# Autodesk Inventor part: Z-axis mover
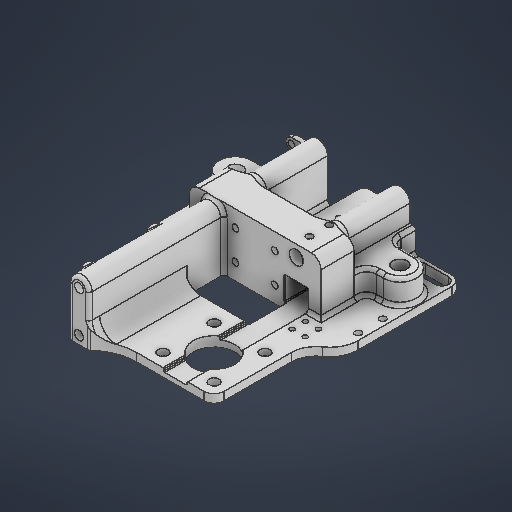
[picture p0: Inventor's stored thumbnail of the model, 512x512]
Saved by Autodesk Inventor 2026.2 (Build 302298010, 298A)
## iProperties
Created: 2026-04
Part Number: Z-axis mover
Material: 일반
Document SubType Name: Modeling
Designer: work
Density: 1 g/cm^3
Appearance: 기본값
Author: work
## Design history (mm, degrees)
sketch "스케치1"
  geometry: L1 (0, 0)-(8, 0); L2 (0, 0)-(0, 8); L3 (0, 0)-(-8, 0); L4 (0, 0)-(0, -8); L5 (0, 0)-(50, 0); L6 (0, 0)-(-50, 0); L7 (0, 0)-(0, 50); L8 (25, 0)-(25, -380); L9 (-25, 0)-(-25, -380); L10 (-25, 0)-(-25, 70); L11 (25, -380)-(-25, -380); L12 (25, 0)-(25, 0); L13 (25, 0)-(25, 120); L14 (-37.5, -395)-(37.5, -395); L15 (37.5, -395)-(37.5, -365); L16 (37.5, -365)-(-37.5, -365); L17 (-37.5, -365)-(-37.5, -395); L18 (-37.5, -395)-(37.5, -365); L19 (37.5, -395)-(-37.5, -365); L20 (-62.5, 38)-(62.5, 38); L21 (62.5, 38)-(62.5, -38); L22 (62.5, -38)-(-62.5, -38); L23 (-62.5, -38)-(-62.5, 38); L24 (-62.5, 38)-(62.5, -38); L25 (62.5, 38)-(-62.5, -38); L26 (62.5, -25)-(-62.5, -25); L27 (17, 38)-(-17, 38); L28 (-17, 38)-(-17, 61); L29 (-17, 61)-(17, 61); L30 (17, 61)-(17, 38); L31 (-22, 60.236)-(-22, 100); L32 (-22, 100)-(-28, 100); L33 (-28, 100)-(-28, -380); L34 (-28, -380)-(-22, -380); L35 (-22, -380)-(-22, 100); L36 (-40, 38)-(40, 38); L37 (40, 38)-(40, 18); L38 (40, 18)-(-40, 18); L39 (-40, 18)-(-40, 38); C1 r 5.25 at (0, 0); C2 r 11.3 at (0, 0); C3 r 2 at (8, 0); C4 r 2 at (0, 8); C5 r 2 at (-8, 0); C6 r 2 at (0, -8); C7 r 4.4 at (50, 0); C8 r 4.4 at (-50, 0); C9 r 4 at (0, 50); 7 further points
  constraints: 78 end point, 12 midpoint, 10 parallel, 9 centre point, 9 coincident, 8 horizontal, 6 perpendicular, 6 point on line, 5 vertical, 2 symmetric about line, 1 collinear, 22 other
  dimensions: "d0" = 10.5 diameter of C1; "d1" = 22.6 diameter of C2; "d2" = 8 distance of L1.start L1.end; "d3" = 4 diameter of C3; "d6" = 360 deg dimension on C1.centre L1.end (derived); "d8" = 50 distance of L4.start L5.end; "d9" = 8.8 diameter of C7; "d10" = 50 distance of L4.start L7.end; "d11" = 8 diameter of C9; "d12" = 12 distance of point (0, 38) L7.end; "d15" = 450 distance of L9.end L10.end; "d16" = 25 distance from line of point (0, 0) L8; "d17" = 25 distance from line of L10 C1.centre; "d19" = 500 distance of L8.end L13.end; "d20" = 120 vertical distance of point (0, 0) L13.end; "d21" = 75 distance between parallel lines of L17 L15; "d22" = 30 distance of L14.end L15.end; "d23" = 125 distance between parallel lines of L23 L21; "d24" = 25 distance from line of point (0, 0) L26; "d25" = 340 distance between parallel lines of L16 L26 (derived); "d26" = 34 distance of L28.end L29.end; "d27" = 23 distance of L27.end L28.end; "d30" = 6 distance between parallel lines of L33 L35; "d31" = 80 distance of L37.end L38.end; "d32" = 20 distance of L36.end L37.end; "d60" = 30 distance of L10.end point (-25, 100)
  node "스케치 - 원형 패턴1" dims "d6" = 360 deg (derived)
extrude "돌출1" new body sketch "스케치1" distance "d33" = 6; taper "d34" = 0 deg
extrude "돌출2" join sketch "스케치1" distance "d35" = 4; taper "d36" = 0 deg
extrude "돌출3" join sketch "스케치1" distance "d37" = 38; taper "d38" = 0 deg
sketch "스케치2"
  geometry: L1 (102.5, 6)-(22.5, 6) reference; L2 (87.5, 6)-(87.5, 31); L3 (93.5, 6)-(93.5, 31); L4 (81.5, 31)-(81.5, 6); L5 (0, 0)-(125, 0) reference; L6 (62.5, 6)-(37.5, 6); L7 (37.5, 6)-(37.5, 31); L8 (37.5, 31)-(62.5, 31); L9 (62.5, 31)-(62.5, 6); L10 (30.5, 4)-(44.5, 4); L11 (44.5, 4)-(44.5, 18); L12 (44.5, 18)-(30.5, 18); L13 (30.5, 18)-(30.5, 4); L14 (30.5, 4)-(44.5, 18); L15 (44.5, 4)-(30.5, 18); L16 (44.5, -10.5)-(86.5, -10.5); L17 (86.5, -10.5)-(86.5, 32.5); L18 (86.5, 32.5)-(44.5, 32.5); L19 (44.5, 32.5)-(44.5, -10.5); L20 (44.5, -10.5)-(86.5, 32.5); L21 (86.5, -10.5)-(44.5, 32.5); L22 (47.5, 32.5)-(47.5, -10.5); L23 (37.5, 6)-(37.5, 31); L24 (43.5, 6)-(43.5, 31); L25 (31.5, 31)-(31.5, 6); L26 (47, 1.5)-(28, 1.5); L27 (28, 1.5)-(28, 20.5); L28 (28, 20.5)-(47, 20.5); L29 (47, 20.5)-(47, 1.5); L30 (47, 1.5)-(28, 20.5); L31 (28, 1.5)-(47, 20.5); C1 r 2.75 at (87.5, 6); C2 r 2.75 at (87.5, 31); C3 r 4.25 at (37.5, 31); A1 r 6 centre (87.5, 6) between (81.5, 6) and (93.5, 6); A2 r 6 centre (87.5, 31) between (93.5, 31) and (81.5, 31); A3 r 6 centre (37.5, 6) between (31.5, 6) and (43.5, 6); A4 r 6 centre (37.5, 31) between (43.5, 31) and (31.5, 31); 16 further points
  constraints: 62 end point, 11 midpoint, 10 parallel, 10 tangent, 8 point on circle, 7 centre point, 7 perpendicular, 5 point on line, 4 horizontal, 2 coincident
  dimensions: "d39" = 5.5 diameter of C1; "d40" = 25 distance of L2.start L6.start; "d41" = 25 distance of L2.start L2.end; "d42" = 5.5 diameter of C2; "d43" = 25 distance of L7.end L8.end; "d44" = 25 distance of L6.end L7.end; "d45" = 8.5 diameter of C3; "d46" = 14 distance of L11.end L12.end; "d47" = 14 distance of L10.end L11.end; "d48" = 43 distance of L16.end L17.end; "d50" = 20 distance of L7.end point (37.5, 11); "d51" = 39 distance between parallel lines of L17 L22; "d52" = 3 distance between parallel lines of L22 L19; "d59" = 2.5 distance between parallel lines of L28 L12
extrude "돌출4" join sketch "스케치2" distance "d53" = 145; taper "d54" = 0 deg
extrude "돌출5" cut sketch "스케치2" extent not by distance; stored distance "d55" = 10; taper "d56" = 0 deg
sketch "스케치3"
  geometry: L1 (-31.5, 20.5)-(-31.5, 31) reference; L2 (-43.5, 31)-(-43.5, 20.5) reference; L3 (-30.5, 4)-(-44.5, 4) reference; L4 (-44.5, 18)-(-30.5, 18) reference; L5 (-28, 20.5)-(-31.5, 20.5) reference; L6 (-43.5, 20.5)-(-47, 20.5) reference; L7 (-47, 1.5)-(-41.469, 1.5) reference; L8 (-33.531, 1.5)-(-28, 1.5) reference; L9 (-28, 1.5)-(-28, 20.5) reference; L10 (-30.5, 18)-(-30.5, 4) reference; L11 (-44.5, 4)-(-44.5, 18) reference; L12 (-47, 20.5)-(-47, 1.5) reference; C1 r 6 at (-37.5, 31); A1 r 6 centre (-37.5, 6) between (-41.469, 1.5) and (-33.531, 1.5) reference; A2 r 6 centre (-37.5, 31) between (-31.5, 31) and (-43.5, 31) reference; 5 further points
  constraints: 1 centre point, 1 concentric
extrude "돌출6" cut sketch "스케치3" stored distance "d57" = 145; taper "d58" = 0 deg
sketch "스케치5"
  geometry: L1 (29.25, 38)-(20.75, 38) reference; L2 (18, 38)-(32, 38) reference; L3 (32, 38)-(18, 38) reference; L4 (-25, 38)-(62.5, 38) reference; L5 (40, 38)-(62.5, 38) reference; L6 (-40, 38)-(40, 38) reference; L7 (-62.5, 38)-(-40, 38) reference; L8 (-62.5, 38)-(-25, 38) reference; L9 (-25, 38)-(-31, 38) reference; L10 (-31, 38)-(-19, 38) reference; L11 (-19, 38)-(-25, 38) reference; L12 (25, 38)-(25, 88); L13 (9.5, 103.5)-(40.5, 103.5); L14 (40.5, 103.5)-(40.5, 72.5); L15 (40.5, 72.5)-(9.5, 72.5); L16 (9.5, 72.5)-(9.5, 103.5); L17 (9.5, 103.5)-(40.5, 72.5); L18 (40.5, 103.5)-(9.5, 72.5); L19 (1.5, 111.5)-(48.5, 111.5); L20 (48.5, 111.5)-(48.5, 64.5); L21 (48.5, 64.5)-(1.5, 64.5); L22 (1.5, 64.5)-(1.5, 111.5); L23 (1.5, 111.5)-(48.5, 64.5); L24 (48.5, 111.5)-(1.5, 64.5); L25 (-22.25, 120)-(-22.25, -25) reference; L26 (-31, 38)-(-19, 38) reference; L27 (-31, 38)-(-31, 120) reference; L28 (-19, 120)-(-31, 120) reference; L29 (-19, 38)-(-19, 120) reference; L30 (62.5, 38)-(62.5, -25) reference; L31 (40, 18)-(40, 38) reference; L32 (-62.5, 38)-(-25, 38) reference; L33 (-62.5, -25)-(-62.5, 38) reference; L34 (62.5, -25)-(-62.5, -25) reference; L35 (62.5, 38)-(62.5, -25) reference; L36 (-25, 38)-(62.5, 38) reference; L37 (-19, 38)-(19, 38); L38 (19, 38)-(19, 62); L39 (19, 62)-(-19, 62); L40 (-19, 62)-(-19, 38); L41 (-19, 38)-(-19, 120) reference; C1 r 12.5 at (25, 88); C2 r 2 at (9.5, 72.5); C3 r 2 at (40.5, 103.5); C4 r 2 at (9.5, 103.5); C5 r 2 at (40.5, 72.5); C6 r 2 at (0, -8) reference; C7 r 2 at (8, 0) reference; C8 r 2 at (0, 8) reference; C9 r 2 at (-8, 0) reference; C10 r 5.25 at (0, 0) reference; C11 r 4.4 at (50, 0) reference; C12 r 4.4 at (-50, 0) reference; A1 r 28.971 centre (1.5, 140.471) between (-19, 120) and (1.5, 111.5); A2 r 15 centre (63.5, 64.5) between (48.5, 64.5) and (55.046, 52.109); A3 r 17.08 centre (45.42, 38) between (62.5, 38) and (55.046, 52.109); 15 further points
  constraints: 34 end point, 8 centre point, 6 parallel, 6 point on circle, 5 coincident, 5 midpoint, 4 perpendicular, 4 tangent, 3 horizontal, 2 point on line, 5 other
  dimensions: "d61" = 25 distance from line of point (0, 38) L12; "d62" = 25 diameter of C1; "d63" = 31 distance of L14.end L15.end; "d64" = 31 distance of L13.end L14.end; "d65" = 4 diameter of C2; "d66" = 4 diameter of C3; "d67" = 4 diameter of C4; "d68" = 4 diameter of C5; "d69" = 50 distance of L12.start L12.end; "d70" = 8 distance between parallel lines of L14 L20; "d71" = 15 radius of A2; "d73" = 24 distance of L39.end L37.start
extrude "돌출7" join sketch "스케치5" distance "d74" = 6; taper "d75" = 0 deg
sketch "스케치6"
  geometry: L1 (-81.5, 31)-(-81.5, 0) reference; L2 (-81.5, 0)-(-43.5, 0) reference; L3 (-43.5, 0)-(-43.5, 4) reference; L4 (-30.5, 6)-(-22.5, 6) reference; L5 (-44.5, 18)-(-44.5, 4) reference; L6 (-30.5, 18)-(-44.5, 18) reference; L7 (-30.5, 6)-(-30.5, 18) reference; L8 (-22.5, 6)-(-22.5, 38) reference; L9 (-102.5, 38)-(-22.5, 38) reference; L10 (-102.5, 6)-(-102.5, 38) reference; L11 (-125, 6)-(-102.5, 6) reference; L12 (-125, 0)-(-125, 6) reference; L13 (-125, 0)-(-93.5, 0) reference; L14 (-93.5, 0)-(-93.5, 31) reference; L15 (-81.5, 6)-(-81.5, 31) reference; L16 (-93.5, 31)-(-93.5, 0) reference; L17 (0, 0)-(-125, 0) reference; L18 (-93.5, 6)-(-81.5, 6); L19 (-81.5, 6)-(-81.5, 0); L20 (-81.5, 0)-(-93.5, 0); L21 (-93.5, 0)-(-93.5, 6); L22 (-81.5, 0)-(-93.5, 0) reference; L23 (-81.5, 0)-(-81.5, 6) reference; L24 (-90.25, 6)-(-84.75, 6) reference; L25 (-44.5, 4)-(-43.5, 4) reference; C1 r 4.25 at (-37.5, 31) reference; C2 r 2.75 at (-87.5, 31) reference; A1 r 6 centre (-87.5, 31) between (-81.5, 31) and (-93.5, 31) reference; A2 r 6 centre (-87.5, 31) between (-81.5, 31) and (-93.5, 31) reference; A3 r 2.75 centre (-87.5, 6) between (-84.75, 6) and (-90.25, 6) reference; 10 further points
  constraints: 8 end point, 2 parallel, 2 point on line, 1 horizontal, 1 perpendicular
extrude "돌출8" join sketch "스케치6" stored distance "d76" = 6; taper "d77" = 0 deg
sketch "스케치7"
  geometry: L1 (47, 6)-(81.5, 6) reference; L2 (47, 20.5)-(43.5, 20.5) reference; L3 (43.5, 20.5)-(43.5, 31) reference; L4 (31.5, 31)-(31.5, 20.5) reference; L5 (31.5, 20.5)-(28, 20.5) reference; L6 (28, 20.5)-(28, 6) reference; L7 (0, 6)-(28, 6) reference; L8 (0, 0)-(0, 6) reference; L9 (0, 0)-(125, 0) reference; L10 (125, 0)-(125, 6) reference; L11 (93.5, 6)-(125, 6) reference; L12 (93.5, 6)-(93.5, 31) reference; L13 (81.5, 31)-(81.5, 6) reference; L14 (44.5, 18)-(44.5, 4) reference; L15 (44.5, 4)-(30.5, 4) reference; L16 (30.5, 4)-(30.5, 18) reference; L17 (30.5, 18)-(44.5, 18) reference; L18 (43.5, 4)-(30.5, 4) reference; L19 (43.5, 4)-(43.5, 6) reference; L20 (30.5, 6)-(43.5, 6) reference; L21 (30.5, 4)-(30.5, 6) reference; L22 (81.5, 0)-(43.5, 0) reference; L23 (81.5, 0)-(81.5, 6) reference; L24 (43.5, 6)-(81.5, 6) reference; L25 (43.5, 0)-(43.5, 6) reference; L26 (47, 6)-(47, 20.5) reference; C1 r 2.75 at (87.5, 31) reference; C2 r 2.75 at (87.5, 6) reference; C3 r 2.75 at (87.5, 31) reference; A1 r 6 centre (37.5, 31) between (43.5, 31) and (31.5, 31) reference; A2 r 6 centre (87.5, 31) between (93.5, 31) and (81.5, 31) reference; 4 further points
extrude "돌출9" cut sketch "스케치7" extent not by distance; stored distance "d78" = 0; taper "d79" = 0 deg
sketch "스케치8"
  geometry: L1 (50.5, 10)-(74.5, 10); L2 (74.5, 10)-(74.5, 28); L3 (74.5, 28)-(50.5, 28); L4 (50.5, 28)-(50.5, 10); L5 (50.5, 10)-(74.5, 28); L6 (74.5, 10)-(50.5, 28); L7 (102.5, 38)-(22.5, 38) reference; L8 (62.5, 38)-(62.5, 0); C1 r 2 at (50.5, 28); C2 r 2 at (50.5, 10); C3 r 2 at (74.5, 10); C4 r 2 at (74.5, 28); 1 further point
  constraints: 14 end point, 4 centre point, 4 coincident, 4 midpoint, 2 parallel, 1 horizontal, 1 perpendicular, 1 vertical
  dimensions: "d80" = 24 distance of L3.end L2.end; "d81" = 18 distance of L2.end L1.end; "d82" = 4 diameter of C1; "d83" = 4 diameter of C2; "d84" = 4 diameter of C3; "d85" = 4 diameter of C4
extrude "돌출10" cut sketch "스케치8" extent not by distance; stored distance "d86" = 18 (derived); taper "d87" = 0 deg
sketch "스케치9"
  geometry: L1 (59, -32)-(59, -7) reference; L2 (71, -7)-(71, -32) reference; L3 (80, -32)-(71, -32) reference; L4 (80, -32)-(80, 0) reference; L5 (0, 0)-(80, 0) reference; L6 (0, -32)-(0, 0) reference; L7 (5.5, -32)-(0, -32) reference; L8 (5.5, -32)-(5.5, -17.5) reference; L9 (5.5, -17.5)-(9, -17.5) reference; L10 (9, -17.5)-(9, -7) reference; L11 (21, -7)-(21, -17.5) reference; L12 (21, -17.5)-(24.5, -17.5) reference; L13 (59, -32)-(24.5, -32) reference; L14 (24.5, -17.5)-(24.5, -32) reference; C1 r 2 at (28, -28) reference; C2 r 2 at (52, -28) reference; C3 r 2 at (28, -10) reference; C4 r 2 at (52, -10) reference; C5 r 2 at (52, -28) reference; A1 r 6 centre (65, -7) between (71, -7) and (59, -7) reference; A2 r 6 centre (15, -7) between (21, -7) and (9, -7) reference; 5 further points
  constraints: 4 coincident
hole "구멍1" sketch "스케치9" at (52, -10), (28, -10), (28, -28), (52, -28) diameter "d88" = 4; stored, may be unused: countersink angle "d92" = 90 deg, drill point angle "d94" = 0 deg; dims "d89" = 6, "d90" = 6.2, "d91" = 4, "d93" = 8
sketch "스케치10"
  geometry: L1 (32, -98.356)-(32, -111.5) reference; L2 (32, -111.5)-(48.5, -111.5) reference; L3 (48.5, -111.5)-(48.5, -64.5) reference; L4 (62.5, -38)-(62.5, 25) reference; L5 (62.5, 25)-(34.5, 25) reference; L6 (34.5, 25)-(34.5, -18) reference; L7 (34.5, -18)-(40, -18) reference; L8 (40, -18)-(40, -38) reference; L9 (32, -38)-(40, -38) reference; L10 (32, -38)-(32, -77.644) reference; L11 (-31, -18)-(-31, 25) reference; L12 (-31, 25)-(-62.5, 25) reference; L13 (-62.5, 25)-(-62.5, -38) reference; L14 (-62.5, -38)-(-40, -38) reference; L15 (-40, -38)-(-40, -18) reference; L16 (-40, -18)-(-31, -18) reference; L17 (-50, -10)-(-31, -10); L18 (-50, 10)-(-31, 10); L19 (50, 10)-(34.5, 10); L20 (50, -10)-(34.5, -10); C1 r 4.4 at (50, 0) reference; C2 r 2 at (40.5, -72.5) reference; C3 r 2 at (40.5, -103.5) reference; C4 r 4.4 at (-50, 0) reference; A1 r 15 centre (63.5, -64.5) between (55.046, -52.109) and (48.5, -64.5) reference; A2 r 17.08 centre (45.42, -38) between (55.046, -52.109) and (62.5, -38) reference; A3 r 12.5 centre (25, -88) between (32, -98.356) and (32, -77.644) reference; A4 r 10 centre (-50, 0) between (-50, -10) and (-50, 10); A5 r 10 centre (50, 0) between (50, 10) and (50, -10); 1 further point
  constraints: 8 end point, 4 perpendicular, 4 point on circle, 4 point on line, 4 tangent, 2 centre point, 2 coincident
  dimensions: "d95" = 20 diameter of A4; "d96" = 20 diameter of A5
extrude "돌출11" join sketch "스케치10" stored distance "d97" = 10; taper "d98" = 0 deg
fillet "모깎기1" dims "d99" = 6
sketch "스케치11"
  geometry: C1 r 4.25 at (0, 0) reference; 1 further point
extrude "돌출12" cut sketch "스케치11" extent not by distance; stored distance "d100" = 0; taper "d101" = 0 deg
fillet "모깎기2" dims "d102" = 2
fillet "모깎기3" dims "d103" = 0.5
chamfer "모따기1" distance "d104" = 1; stored, may be unused: second distance "d105" = 2, angle "d106" = 45 deg
sketch "스케치12"
  geometry: L1 (17.5, -61.936)-(17.5, -78) reference; L2 (17, -62)-(-17, -62) reference; L3 (-19, -60)-(-19, -118) reference; L4 (-21, -120)-(-19.813, -120) reference; L5 (1.5, -111.5)-(17.5, -111.5) reference; L6 (17.5, -98)-(17.5, -111.5) reference; L7 (42, -40)-(42, -17.621) reference; L8 (32.5, -78)-(32.5, -40) reference; L9 (32.5, -111.5)-(32.5, -98) reference; L10 (32.5, -111.5)-(42.5, -111.5) reference; L11 (48.5, -105.5)-(48.5, -64.5) reference; L12 (62.5, -38)-(62.5, 19) reference; L13 (56.5, 25)-(36.5, 25) reference; L14 (36.5, 16)-(36.5, 25) reference; L15 (50, 12)-(40.5, 12) reference; L16 (45.657, -12)-(50, -12) reference; L17 (42, -40)-(42, -17.621) reference; L18 (32.5, -40)-(42, -40) reference; C1 r 2 at (9.5, -72.5) reference; C2 r 2 at (9.5, -103.5) reference; C3 r 2 at (40.5, -103.5) reference; C4 r 2 at (40.5, -72.5) reference; C5 r 2 at (40.5, -103.5) reference; A1 r 2 centre (17, -60) between (17, -62) and (17.5, -61.936) reference; A2 r 2 centre (-17, -60) between (-19, -60) and (-17, -62) reference; A3 r 2 centre (-21, -118) between (-21, -120) and (-19, -118) reference; A4 r 2 centre (-19.813, -118) between (-19.813, -120) and (-18.437, -119.451) reference; A5 r 28.971 centre (1.5, -140.471) between (1.5, -111.5) and (-18.437, -119.451) reference; A6 r 12.5 centre (25, -88) between (17.5, -78) and (17.5, -98) reference; A7 r 12.5 centre (25, -88) between (32.5, -98) and (32.5, -78) reference; A8 r 6 centre (42.5, -105.5) between (42.5, -111.5) and (48.5, -105.5) reference; A9 r 15 centre (63.5, -64.5) between (55.046, -52.109) and (48.5, -64.5) reference; A10 r 17.08 centre (45.42, -38) between (55.046, -52.109) and (62.5, -38) reference; A11 r 6 centre (56.5, 19) between (62.5, 19) and (56.5, 25) reference; A12 r 4 centre (40.5, 16) between (36.5, 16) and (40.5, 12) reference; A13 r 12 centre (50, 0) between (50, -12) and (50, 12) reference; A14 r 4 centre (45.657, -16) between (45.657, -12) and (42, -17.621) reference; 5 further points
  constraints: 4 coincident
hole "구멍2" sketch "스케치12" at (9.5, -103.5), (40.5, -103.5), (40.5, -72.5), (9.5, -72.5) diameter "d107" = 4; stored, may be unused: countersink angle "d111" = 90 deg, drill point angle "d113" = 0 deg; dims "d108" = 6, "d109" = 6.2, "d110" = 4, "d112" = 8
fillet "모깎기4" dims "d114" = 10
sketch "스케치13"
  geometry: L1 (78, -30)-(0, -30) reference; L2 (78, 0)-(78, -30) reference; L3 (0, 0)-(78, 0) reference; L4 (0, -30)-(0, 0) reference; L5 (68, 0)-(28, 0); L6 (28, 0)-(28, -25); L7 (28, -25)-(68, -25); L8 (68, -25)-(68, 0); C1 r 4 at (28, 0); C2 r 4 at (28, -25); C3 r 4 at (68, -25); C4 r 4 at (68, 0); 1 further point
  constraints: 8 end point, 4 centre point, 2 parallel, 1 coincident, 1 horizontal, 1 perpendicular, 1 point on line
  dimensions: "d115" = 40 distance of L7.end L6.end; "d116" = 25 distance of L6.end L5.end; "d117" = 10 distance between parallel lines of L2 L8; "d118" = 8 diameter of C1; "d119" = 8 diameter of C2; "d120" = 8 diameter of C3; "d121" = 8 diameter of C4
  node "투영된 루프17"
extrude "돌출13" join sketch "스케치13" stored distance "d122" = 8 (derived); taper "d123" = 0 deg
extrude "돌출14" join sketch "스케치13" distance "d124" = 1.5; taper "d125" = 0 deg
sketch "스케치14"
  geometry: L1 (4, 0)-(36, 0) reference; L2 (-28, 0)-(-4, 0) reference; L3 (-28, -30)-(-28, 0) reference; L4 (50, -30)-(-28, -30) reference; L5 (50, 0)-(50, -30) reference; L6 (44, 0)-(50, 0) reference; C1 r 4 at (40, -25) reference; C2 r 4 at (0, -25) reference; C3 r 2 at (0, 0); C4 r 2 at (0, -25); C5 r 2 at (40, -25); C6 r 2 at (40, 0); A1 r 4 centre (40, 0) between (36, 0) and (44, 0) reference; A2 r 4 centre (0, 0) between (-4, 0) and (4, 0) reference; 1 further point
  constraints: 4 centre point, 4 coincident
  dimensions: "d126" = 4 diameter of C3; "d127" = 4 diameter of C4; "d128" = 4 diameter of C5; "d129" = 4 diameter of C6
  node "투영된 루프18"
extrude "돌출15" cut sketch "스케치14" stored distance "d130" = 1.5; taper "d131" = 0 deg
extrude "돌출16" cut sketch "스케치14" stored distance "d132" = 10; taper "d133" = 0 deg
fillet "모깎기5" dims "d134" = 2
sketch "스케치15"
  geometry: L1 (-21.127, -38)-(34, -38) reference; L2 (25, -38)-(25, -18); C1 r 2 at (25, -18); C2 r 2 at (25, -30); 1 further point
  constraints: 2 centre point, 2 end point, 2 point on line, 1 coincident, 1 vertical
  dimensions: "d135" = 20 distance of L2.start L2.end; "d136" = 25 distance from line of L2 point (0, 0); "d137" = 4 diameter of C1; "d138" = 4 diameter of C2; "d139" = 12 distance of L2.end C2.centre
extrude "돌출17" cut sketch "스케치15" stored distance "d140" = 10; taper "d141" = 0 deg
sketch "스케치16" dims "d145" = 7
  geometry: L1 (13, -21.5)-(13, -1.9); L2 (8, -25)-(31.5, -25) reference; L3 (6, -23)-(6, 0) reference; L4 (13, -5.4)-(6, -5.4); L5 (13, 1.6)-(5.783, 1.6); L6 (13, -18)-(6, -18); L7 (-42.5, -26.5)-(-42.5, -13.5) reference; L8 (-56.5, -27.5)-(-43.5, -27.5) reference; L9 (-57.5, -13.5)-(-57.5, -26.5) reference; L10 (-43.5, -12.5)-(-56.5, -12.5) reference; L11 (31.5, -30)-(-81.5, -30) reference; L12 (31.5, -25)-(31.5, -30) reference; L13 (8, -25)-(31.5, -25) reference; L14 (6, -23)-(6, 0) reference; L15 (-6, 0)-(-6, -23) reference; L16 (-38.5, -25)-(-8, -25) reference; L17 (-40.5, -23)-(-40.5, -12.5) reference; L18 (-42.5, -10.5)-(-44, -10.5) reference; L19 (-44, -10.5)-(-44, 0) reference; L20 (-56, 0)-(-56, -10.5) reference; L21 (-56, -10.5)-(-57.5, -10.5) reference; L22 (-59.5, -12.5)-(-59.5, -23) reference; L23 (-81.5, -25)-(-61.5, -25) reference; L24 (-81.5, -30)-(-81.5, -25) reference; C1 r 2 at (13, -21.5); C2 r 2 at (13, -1.9); C3 r 4.25 at (-50, 0) reference; C4 r 2.75 at (0, 0) reference; C5 r 2.75 at (0, -25) reference; A1 r 3.5 centre (13, -1.9) between (13, -5.4) and (13, 1.6); A2 r 6 centre (0, 0) between (6, 0) and (-6, 0) reference; A3 r 1 centre (-43.5, -13.5) between (-42.5, -13.5) and (-43.5, -12.5) reference; A4 r 1 centre (-43.5, -26.5) between (-43.5, -27.5) and (-42.5, -26.5) reference; A5 r 1 centre (-56.5, -26.5) between (-57.5, -26.5) and (-56.5, -27.5) reference; A6 r 1 centre (-56.5, -13.5) between (-56.5, -12.5) and (-57.5, -13.5) reference; A7 r 2 centre (8, -23) between (6, -23) and (8, -25) reference; A8 r 6 centre (0, 0) between (6, 0) and (-6, 0) reference; A9 r 2 centre (-8, -23) between (-8, -25) and (-6, -23) reference; A10 r 2 centre (-38.5, -23) between (-40.5, -23) and (-38.5, -25) reference; A11 r 2 centre (-42.5, -12.5) between (-40.5, -12.5) and (-42.5, -10.5) reference; A12 r 6 centre (-50, 0) between (-44, 0) and (-56, 0) reference; A13 r 2 centre (-57.5, -12.5) between (-57.5, -10.5) and (-59.5, -12.5) reference; A14 r 2 centre (-61.5, -23) between (-61.5, -25) and (-59.5, -23) reference; 5 further points
  constraints: 8 end point, 4 point on line, 3 centre point, 3 coincident, 3 perpendicular, 3 point on circle, 2 horizontal, 1 tangent, 1 vertical, 3 other
  dimensions: "d142" = 4 diameter of C1; "d143" = 4 diameter of C2; "d144" = 7 diameter of A1; "d146" = 19.6 distance of L1.start L1.end; "d147" = 7 distance from line of L3 L1.start
extrude "돌출18" join sketch "스케치16" distance "d148" = 3; taper "d149" = 0 deg
fillet "모깎기6" dims "d150" = 1
sketch "스케치17"
  geometry: L1 (0, 0)-(0, 25); L2 (13.5, 25)-(-17, 25) reference; L3 (7.5, 21)-(-7.5, 21); L4 (58.5, -34)-(58.5, -19); L5 (62.5, -38)-(62.5, 19) reference; C1 r 2 at (-7.5, 21); C2 r 2 at (7.5, 21); C3 r 2 at (58.5, -34); C4 r 2 at (58.5, -19); 1 further point
  constraints: 6 end point, 4 centre point, 4 coincident, 2 point on line, 2 vertical, 1 horizontal, 1 midpoint
  dimensions: "d151" = 15 distance of L3.start L3.end; "d152" = 4 diameter of C1; "d153" = 4 diameter of C2; "d154" = 4 distance between parallel lines of L2 L3; "d155" = 15 distance of L4.start L4.end; "d156" = 4 diameter of C3; "d157" = 4 diameter of C4; "d158" = 4 distance between parallel lines of L5 L4; "d159" = 4 horizontal distance of L5.start L4.start
extrude "돌출19" cut sketch "스케치17" extent not by distance; stored distance "d160" = 0; taper "d161" = 0 deg
sketch "스케치18"
  geometry: L1 (-42, -17.621)-(-42, -38) reference; L2 (-50, -12)-(-45.657, -12) reference; C1 r 16 at (-60, -30); 1 further point
  constraints: 1 centre point
  dimensions: "d162" = 32 diameter of C1; "d163" = 2 distance edge to line of C1 L1; "d164" = 2 distance edge to line of C1 L2
extrude "돌출20" cut sketch "스케치18" distance "d165" = 2; taper "d166" = 0 deg
sketch "스케치19"
  geometry: L1 (56.5, 19)-(42.5, 19); L2 (56.5, 23)-(42.5, 23); L3 (42.5, 15)-(56.5, 15); L4 (36.5, 16)-(36.5, 25) reference; L5 (-56.5, 19)-(-48, 19); L6 (-56.5, 15)-(-48, 15); L7 (-48, 23)-(-56.5, 23); L8 (-46.144, -38)-(-42, -38) reference; L9 (-42, -17.621)-(-42, -38) reference; L10 (-50, -12)-(-45.657, -12) reference; L11 (-37, 12)-(-50, 12) reference; L12 (-33, 21)-(-33, 16) reference; L13 (-41.742, 21)-(-33, 21) reference; L14 (-41.742, 25)-(-56.5, 25) reference; L15 (-62.5, 19)-(-62.5, -14.197) reference; L16 (36.5, -52)-(44.5, -52); L17 (44.5, -52)-(44.5, -44); L18 (44.5, -44)-(36.5, -44); L19 (36.5, -44)-(36.5, -52); L20 (32.5, -40)-(42, -40) reference; L21 (32.5, -78)-(32.5, -40) reference; L22 (13.5, 25)-(13.5, -16.011) reference; L23 (13.5, 25)-(-17, 25) reference; L24 (-17, -12)-(-17, 25) reference; L25 (9.631, -16)-(-9.631, -16) reference; L26 (32.5, -78)-(32.5, -40) reference; L27 (32.5, -111.5)-(32.5, -98) reference; L28 (32.5, -111.5)-(42.5, -111.5) reference; L29 (48.5, -105.5)-(48.5, -64.5) reference; L30 (62.5, -38)-(62.5, 19) reference; L31 (56.5, 25)-(36.5, 25) reference; L32 (36.5, 16)-(36.5, 25) reference; L33 (50, 12)-(40.5, 12) reference; L34 (45.657, -12)-(50, -12) reference; L35 (42, -40)-(42, -17.621) reference; L36 (32.5, -40)-(42, -40) reference; L37 (-41.742, 25)-(-41.742, 21) reference; C1 r 1.5 at (36.5, -52); C2 r 1.5 at (36.5, -44); C3 r 1.5 at (44.5, -44); C4 r 1.5 at (44.5, -52); A1 r 4 centre (56.5, 19) between (56.5, 15) and (56.5, 23); A2 r 4 centre (42.5, 19) between (42.5, 23) and (42.5, 15); A3 r 6 centre (56.5, 19) between (62.5, 19) and (56.5, 25) reference; A4 r 4 centre (-56.5, 19) between (-56.5, 23) and (-56.5, 15); A5 r 4 centre (-48, 19) between (-48, 15) and (-48, 23); A6 r 6 centre (-56.5, 19) between (-56.5, 25) and (-62.5, 19) reference; A7 r 16 centre (-60, -30) between (-46.144, -38) and (-62.5, -14.197) reference; A8 r 4 centre (-45.657, -16) between (-42, -17.621) and (-45.657, -12) reference; A9 r 12 centre (-50, 0) between (-50, 12) and (-50, -12) reference; A10 r 4 centre (-37, 16) between (-37, 12) and (-33, 16) reference; A11 r 6 centre (-56.5, 19) between (-56.5, 25) and (-62.5, 19) reference; A12 r 4 centre (-13, -12) between (-17, -12) and (-13.912, -15.895) reference; A13 r 12.5 centre (25, -88) between (32.5, -98) and (32.5, -78) reference; A14 r 6 centre (42.5, -105.5) between (42.5, -111.5) and (48.5, -105.5) reference; A15 r 15 centre (63.5, -64.5) between (55.046, -52.109) and (48.5, -64.5) reference; A16 r 17.08 centre (45.42, -38) between (55.046, -52.109) and (62.5, -38) reference; A17 r 6 centre (56.5, 19) between (62.5, 19) and (56.5, 25) reference; A18 r 4 centre (40.5, 16) between (36.5, 16) and (40.5, 12) reference; A19 r 12 centre (50, 0) between (50, -12) and (50, 12) reference; A20 r 4 centre (45.657, -16) between (45.657, -12) and (42, -17.621) reference; 8 further points
  constraints: 24 end point, 10 point on circle, 8 centre point, 8 tangent, 4 coincident, 4 parallel, 3 horizontal, 3 midpoint, 2 concentric, 1 perpendicular, 4 other
  dimensions: "d167" = 8 diameter of A2; "d168" = 2 distance from line of point (38.5, 19) L4; "d169" = 8 diameter of A5; "d171" = 3 diameter of C1; "d172" = 3 diameter of C2; "d173" = 3 diameter of C3; "d174" = 3 diameter of C4; "d175" = 8 distance of L16.end L17.end; "d176" = 8 distance of L17.end L18.end; "d177" = 4 distance between parallel lines of L20 L18; "d178" = 4 distance from line of L21 point (36.5, -48)
extrude "돌출21" cut sketch "스케치19" extent not by distance; stored distance "d179" = 0; taper "d180" = 0 deg
sketch "스케치20"
  geometry: L1 (13.5, 25)-(-17, 25) reference; L2 (-17, 25)-(13.5, 25); L3 (13.5, 25)-(13.5, 45); L4 (13.5, 45)-(-17, 45); L5 (-17, 45)-(-17, 25); L6 (13.5, 25)-(13.5, -16.011) reference; L7 (-17, 25)-(13.5, 25); L8 (13.5, 25)-(13.5, 23.5); L9 (13.5, 23.5)-(-17, 23.5); L10 (-17, 23.5)-(-17, 25); 1 further point
  constraints: 16 end point, 4 parallel, 2 horizontal, 2 perpendicular, 2 point on line
  dimensions: "d181" = 20 distance between parallel lines of L2 L4; "d182" = 1.5 distance between parallel lines of L1 L9
extrude "돌출22" join sketch "스케치20" stored distance "d183" = 10; taper "d184" = 0 deg
chamfer "모따기2" distance "d185" = 1; stored, may be unused: second distance "d186" = 2, angle "d187" = 45 deg
fillet "모깎기7" dims "d188" = 3
node "솔리드1"
node "투영된 루프1"
node "투영된 루프2"
node "투영된 루프3"
node "투영된 루프4"
node "투영된 루프5"
node "투영된 루프6"
node "투영된 루프7"
node "투영된 루프8"
node "투영된 루프9"
node "투영된 루프10"
node "투영된 루프11"
node "투영된 루프12"
node "투영된 루프13"
node "투영된 루프14"
node "투영된 루프15"
node "투영된 루프16"
node "투영된 루프19"
node "투영된 루프20"
feature "A9D066F2-1C7D-4E18-AEED-F7BC21143FA4" dims "d88" = 4, "d89" = 6, "d90" = 6.2, "d91" = 4, "d92" = 90 deg, "d93" = 8, "d94" = 0
